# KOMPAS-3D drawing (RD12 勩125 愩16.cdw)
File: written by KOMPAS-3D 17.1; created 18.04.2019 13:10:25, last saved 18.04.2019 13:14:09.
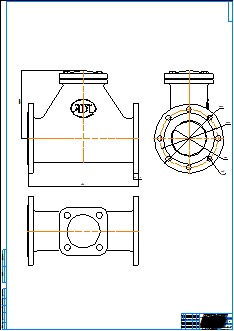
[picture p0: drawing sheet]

Sheet 1: A0, portrait

Title block, sheet 1: name: RD12 Ду125 Ру16; material: Внимание! Данный продукт является объектом авторского права ООО «Торговый Дом АДЛ». / Запрещается изменение, копирование, распространение / (в том числе путем копирования на другие сайты и ресурсы в Интернете) / или любое иное использование информации и объектов без предварительного / согласия правообладателя (ООО «Торговый Дом АДЛ»).; mass: 84,28; sheets: 1; organisation: ООО "Торговый дом АДЛ"; sheet format: A0

Views: Вид 1, Проекционный вид 2, Проекционный вид 3
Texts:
  user
Dimensions and other numbers on the sheet: 16; 3; 394; 243,38; 210; 250; 125; 19; 8 отв.; 1:1; 1; 84,28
